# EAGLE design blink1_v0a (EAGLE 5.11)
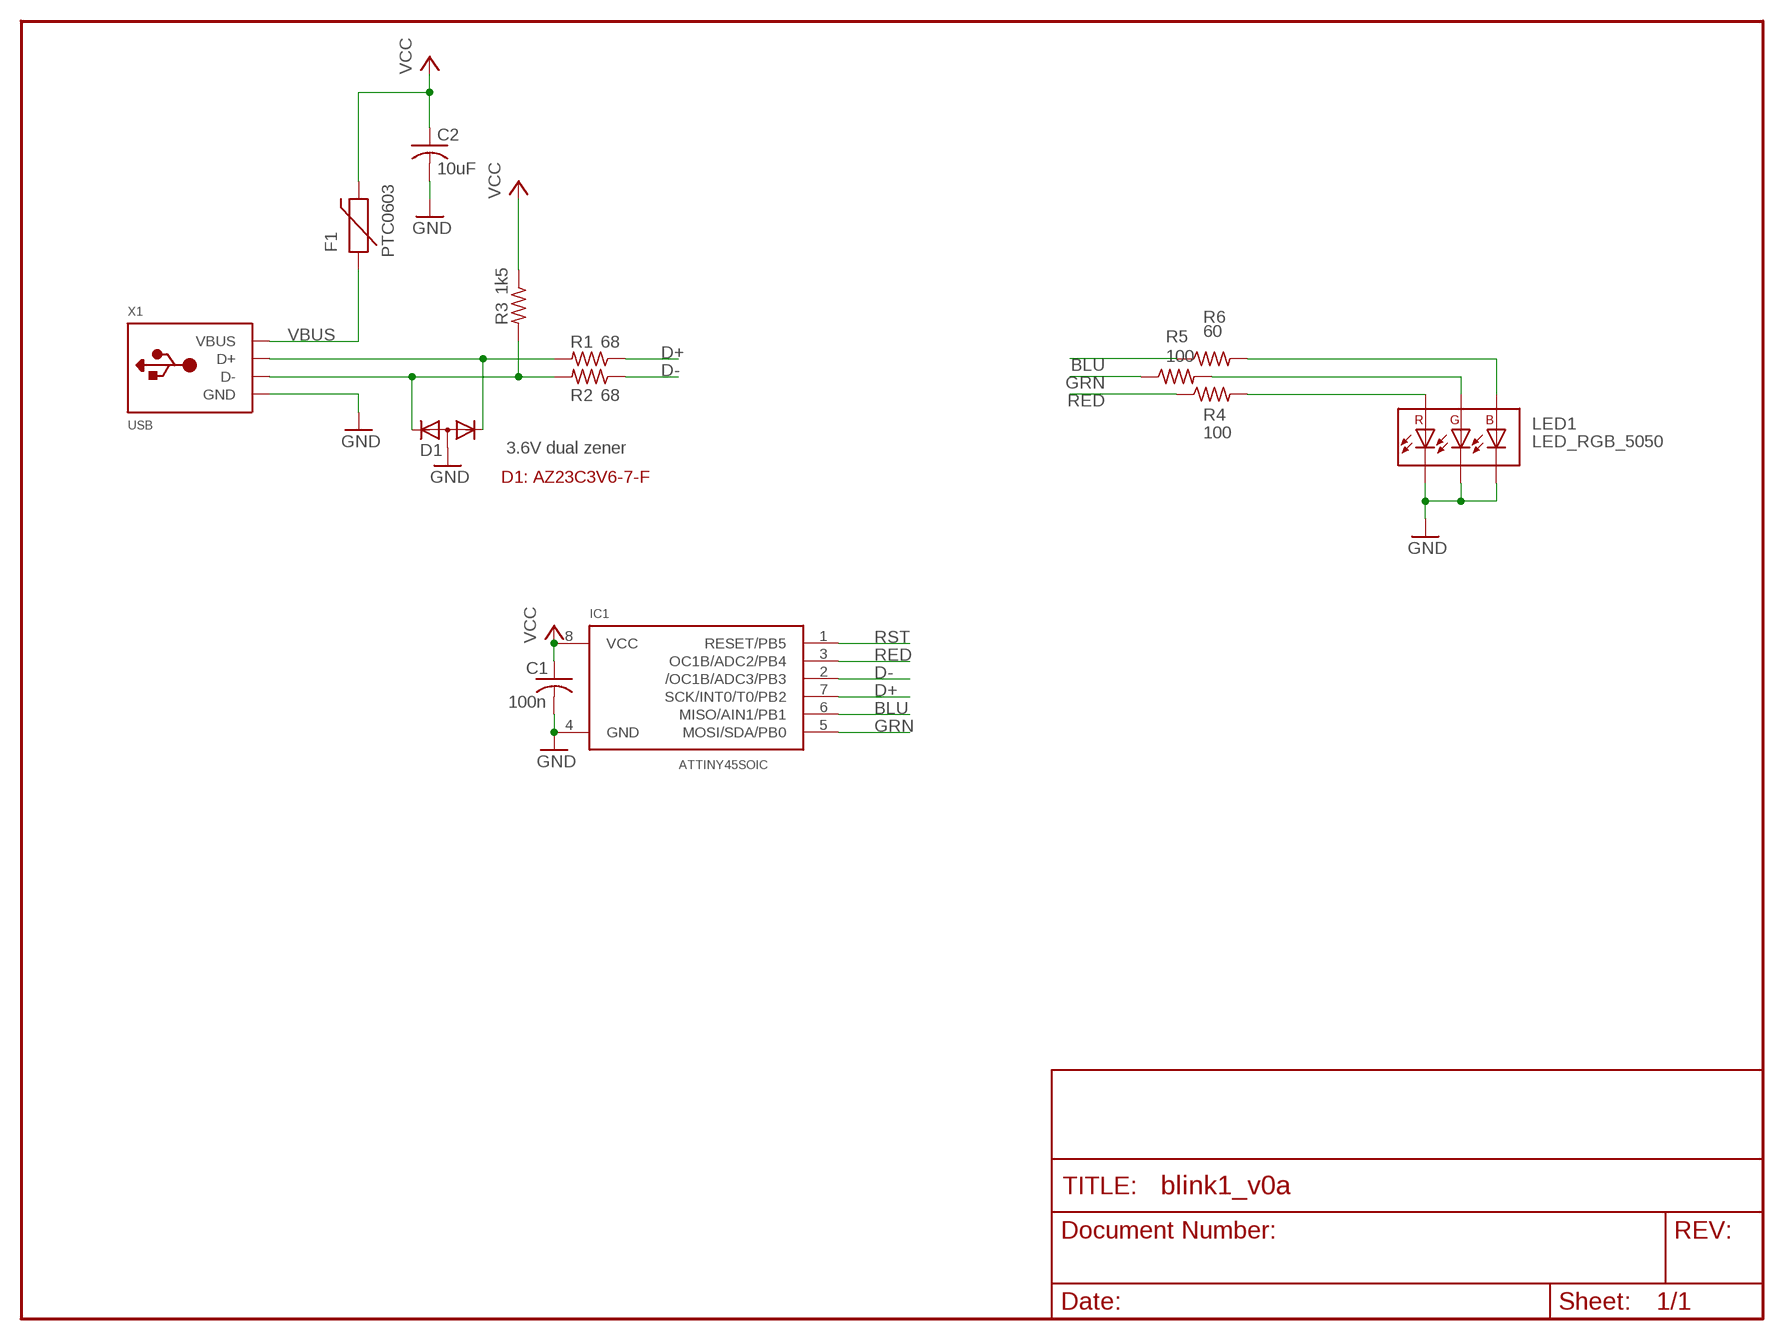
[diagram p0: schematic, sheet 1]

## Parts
C1  100n  C-USC0603  [C0603]
C2  10uF  C-USC0603  [C0603]
D1  3.6V dual zener  DIODE-2CA|ACSOT23  [SOT23]
F1  PTC0603  [0603]
IC1  ATTINY45SOIC  [SO08-EIAJ]
LED1  LED_RGB_5050  [LED_5050]
R1  68  R-US_R0603  [R0603]
R2  68  R-US_R0603  [R0603]
R3  1k5  R-US_R0603  [R0603]
R4  100  R-US_R0603  [R0603]
R5  100  R-US_R0603  [R0603]
R6  60  R-US_R0603  [R0603]
X1  USB  [MOLEX-48037-1000]

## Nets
BLU: IC1.6(MISO/AIN1/PB1) R6.1
D+: IC1.7(SCK/INT0/T0/PB2) R1.1
D-: IC1.2(/OC1B/ADC3/PB3) R2.1
GND: C1.2 C2.2 D1.3(A) IC1.4(GND) LED1.P$4(C2) LED1.P$5(C1) LED1.P$6(C0) X1.4(GND)
GRN: IC1.5(MOSI/SDA/PB0) R5.1
N$4: D1.1(K1) R1.2 X1.3(D+)
N$5: D1.2(K2) R2.2 R3.2 X1.2(D-)
RBLU: LED1.P$3(A2) R6.2
RED: IC1.3(OC1B/ADC2/PB4) R4.1
RGRN: LED1.P$2(A1) R5.2
RRED: LED1.P$1(A0) R4.2
RST: IC1.1(RESET/PB5)
VBUS: F1.1 X1.1(VBUS)
VCC: C1.1 C2.1 F1.2 IC1.8(VCC) R3.1

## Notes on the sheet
- D1: AZ23C3V6-7-F

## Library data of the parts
C1 C2 = rcl:C-US: CAPACITOR, American symbol
D1 = diode:DIODE-2CA|AC: Dual DIODE Cathode-Anode|Anode-Cathode
F1 = SparkFun-20110517:PTC: Resettable Fuse PTC
IC1 = todstuff:ATTINY45
LED1 = todstuff:LED_RGB_5050
R1-R6 = rcl:R-US_: RESISTOR, American symbol
X1 = todstuff:USB

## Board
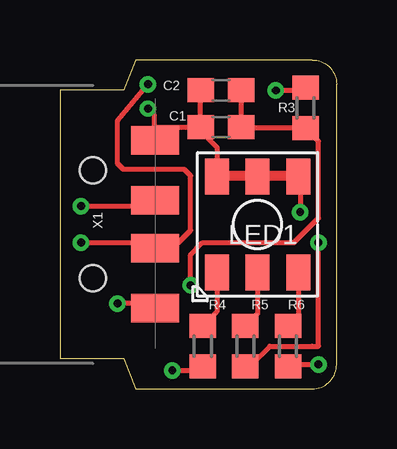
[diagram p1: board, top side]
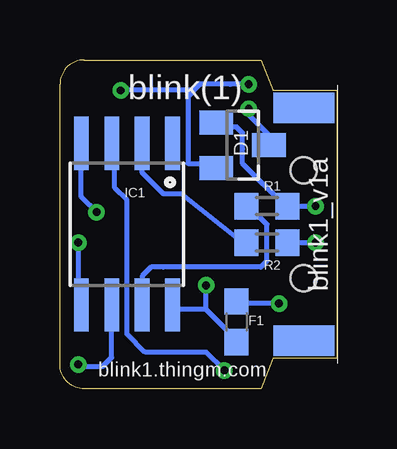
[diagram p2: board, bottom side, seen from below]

Size 11.55 x 13.72 mm. Coordinates in mm from the lower left corner, seen from the top.
Outline: 0,1.27 2.66,1.27 3.16,0 10.53,0 arc90 11.55,1.02 11.55,12.7 arc90 10.53,13.72 3.16,13.72 2.66,12.45 0,12.45 0,1.27
Copper layers (1*16): Top 0.0356mm / dielectric 1.5011mm / Bottom 0.0356mm
Design rules "LaenPCBOrder *": minimum track width 8mil, minimum drill 13mil, track to track 6mil, track to pad 8mil, pad to pad 8mil, via to via 8mil, smd to smd 6mil, copper to edge 15mil, drill to drill 8mil, minimum pad ring 7mil, minimum via ring 7mil, stop-mask expansion 4mil, vias tented up to drill 25mil, thermal gap 10mil

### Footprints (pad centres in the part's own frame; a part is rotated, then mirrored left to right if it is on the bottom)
C0603 = smd 1.1 x 1: 1 -0.85,0; 2 0.85,0
SOT23 = smd 1 x 1.4: 1 -0.95,-1.1; 2 0.95,-1.1; 3 0,1.1
0603 = smd 1.1 x 1: 1 -0.85,0; 2 0.85,0
SO08-EIAJ = smd 0.61 x 2.21: 1 -1.905,-3.378; 2 -0.635,-3.378; 3 0.635,-3.378; 4 1.905,-3.378; 5 1.905,3.353; 6 0.635,3.353; 7 -0.635,3.353; 8 -1.905,3.353
LED_5050 = smd 1 x 1.5: P$1 1.7,2; P$2 0,2; P$3 -1.7,2; P$4 -1.7,-2; P$5 0,-2; P$6 1.7,-2
R0603 = smd 1 x 1.1: 1 -0.85,0; 2 0.85,0
MOLEX-48037-1000 = smd 2 x 1.2: 1 2.6,-3.5; 2 2.6,-1; 3 2.6,1; 4 2.6,3.5 | smd 2.54 x 1.27 bottom: P$1 0,4.85; P$2 0,-4.85 | hole 1.1: 0,2.25; 0,-2.25

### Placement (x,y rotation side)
C1  6.72,10.92 180 top
C2  6.72,12.45 180 top
D1  3.93,10.16 270 bottom
F1  4.18,2.79 270 bottom
IC1  8.75,6.86 180 bottom
LED1  8.24,6.86 180 top
R1  2.91,7.62 0 bottom
R2  2.91,6.1 0 bottom
R3  10.24,11.72 90 top
R4  5.96,1.78 90 top
R5  7.74,1.78 90 top
R6  9.51,1.78 90 top
X1  1.38,6.86 0 top

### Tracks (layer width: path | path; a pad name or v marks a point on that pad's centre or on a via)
BLU  (via drill 0.33)
  Top 0.203: v10.78,1.02 9.77,1.02 R6.1
  Bottom 0.203: IC1.6 9.39,1.31 9.77,0.93 10.95,0.93 v10.78,1.02
D+
  Bottom 0.203: R1.1 3.67,7.62 2.91,6.86 2.91,5.33 3.16,5.08 7.23,5.08 7.74,5.08 8.12,4.7 IC1.7
D-
  Bottom 0.203: R2.1 3.93,6.1 6.47,8.13 7.23,8.13 7.99,8.89 8.12,9.02 IC1.2
GND  (via drill 0.33)
  Top 0.203: v3.67,11.68 3.93,11.43 3.93,10.92 | 3.93,10.92 3.93,10.41 X1.4 3.93,10.92 | 3.93,10.92 5.7,10.92 | LED1.P$6 6.72,8.89 | 9.77,8.89 LED1.P$4 10.02,8.64 v10.02,7.37 | LED1.P$6 6.47,8.89 | 5.7,10.92 6.54,10.08 LED1.P$6 | 5.7,10.92 C1.2 5.87,12.35 C2.2 | 8.24,8.89 LED1.P$5 8.24,8.89
  Top 0.406: 6.72,8.89 8.24,8.89 9.77,8.89
  Bottom 0.203: v3.67,11.68 3.67,11.43 2.91,10.67 2.91,10.16 D1.3 | 10.53,7.87 v10.02,7.37 10.66,8 IC1.4
GRN  (via drill 0.33)
  Top 0.203: v10.78,6.1 10.78,1.78 10.53,1.78 8.75,1.78 7.99,1.02 R5.1
  Bottom 0.203: v10.78,6.1 10.78,3.81 10.78,3.56 IC1.5
N$4  (via drill 0.33)
  Top 0.203: v0.88,7.62 3.93,7.62 X1.3
  Bottom 0.203: 4.94,10.92 D1.1 4.84,10.92 4.18,10.92 3.93,10.67 3.93,10.01 3.93,9.4 2.15,7.62 R1.2 1.89,7.62 v0.88,7.62
N$5  (via drill 0.33)
  Top 0.203: v0.88,6.1 3.93,6.1 X1.2 4.22,6.1 4.94,6.1 5.45,6.6 5.45,8.89 5.2,9.14 2.66,9.14 2.4,9.4 2.4,11.18 v3.67,12.7 | v9.01,12.45 9.77,12.45 R3.2
  Bottom 0.203: v0.88,6.1 1.89,6.1 R2.2 | D1.2 5.2,9.4 6.21,9.4 6.21,12.19 5.83,12.57 | v3.67,12.7 4.43,12.7 5.7,12.7 5.83,12.57 | v9.01,12.45 5.96,12.45 5.83,12.57
RBLU
  Top 0.203: R6.2 9.94,3.06 LED1.P$3
RED  (via drill 0.33)
  Top 0.203: v4.69,0.76 6.21,0.76 R4.1
  Bottom 0.203: v4.69,0.76 5.45,1.52 7.99,1.52 8.75,2.29 8.75,7.87 9.26,8.38 9.26,10.16 IC1.3
RGRN
  Top 0.203: R5.2 8.24,3.14 LED1.P$2
RRED
  Top 0.203: R4.2 6.54,3.21 LED1.P$1
VBUS  (via drill 0.33)
  Top 0.203: v2.4,3.56 3.93,3.56 X1.1
  Bottom 0.203: v2.4,3.56 4.18,3.56 F1.1
VCC  (via drill 0.33)
  Top 0.203: v5.45,4.32 5.45,5.59 5.96,6.1 9.77,6.1 10.78,7.11 10.78,10.33 R3.1 7.63,10.87 C1.1 7.57,12.35 C2.1
  Bottom 0.203: 5.45,3.3 4.18,2.03 F1.2 | 5.45,3.3 6.72,3.3 IC1.8 | 5.45,3.3 v5.45,4.32

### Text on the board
bPlace: blink(1) | blink1_v1a | blink1.thingm.com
